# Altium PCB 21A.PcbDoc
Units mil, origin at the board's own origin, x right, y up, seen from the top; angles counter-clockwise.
Board outline 6000 x 4000 mil, 2 copper layers (Top Layer, Bottom Layer); 43 components, 21 nets, 118 pads, 2 vias.
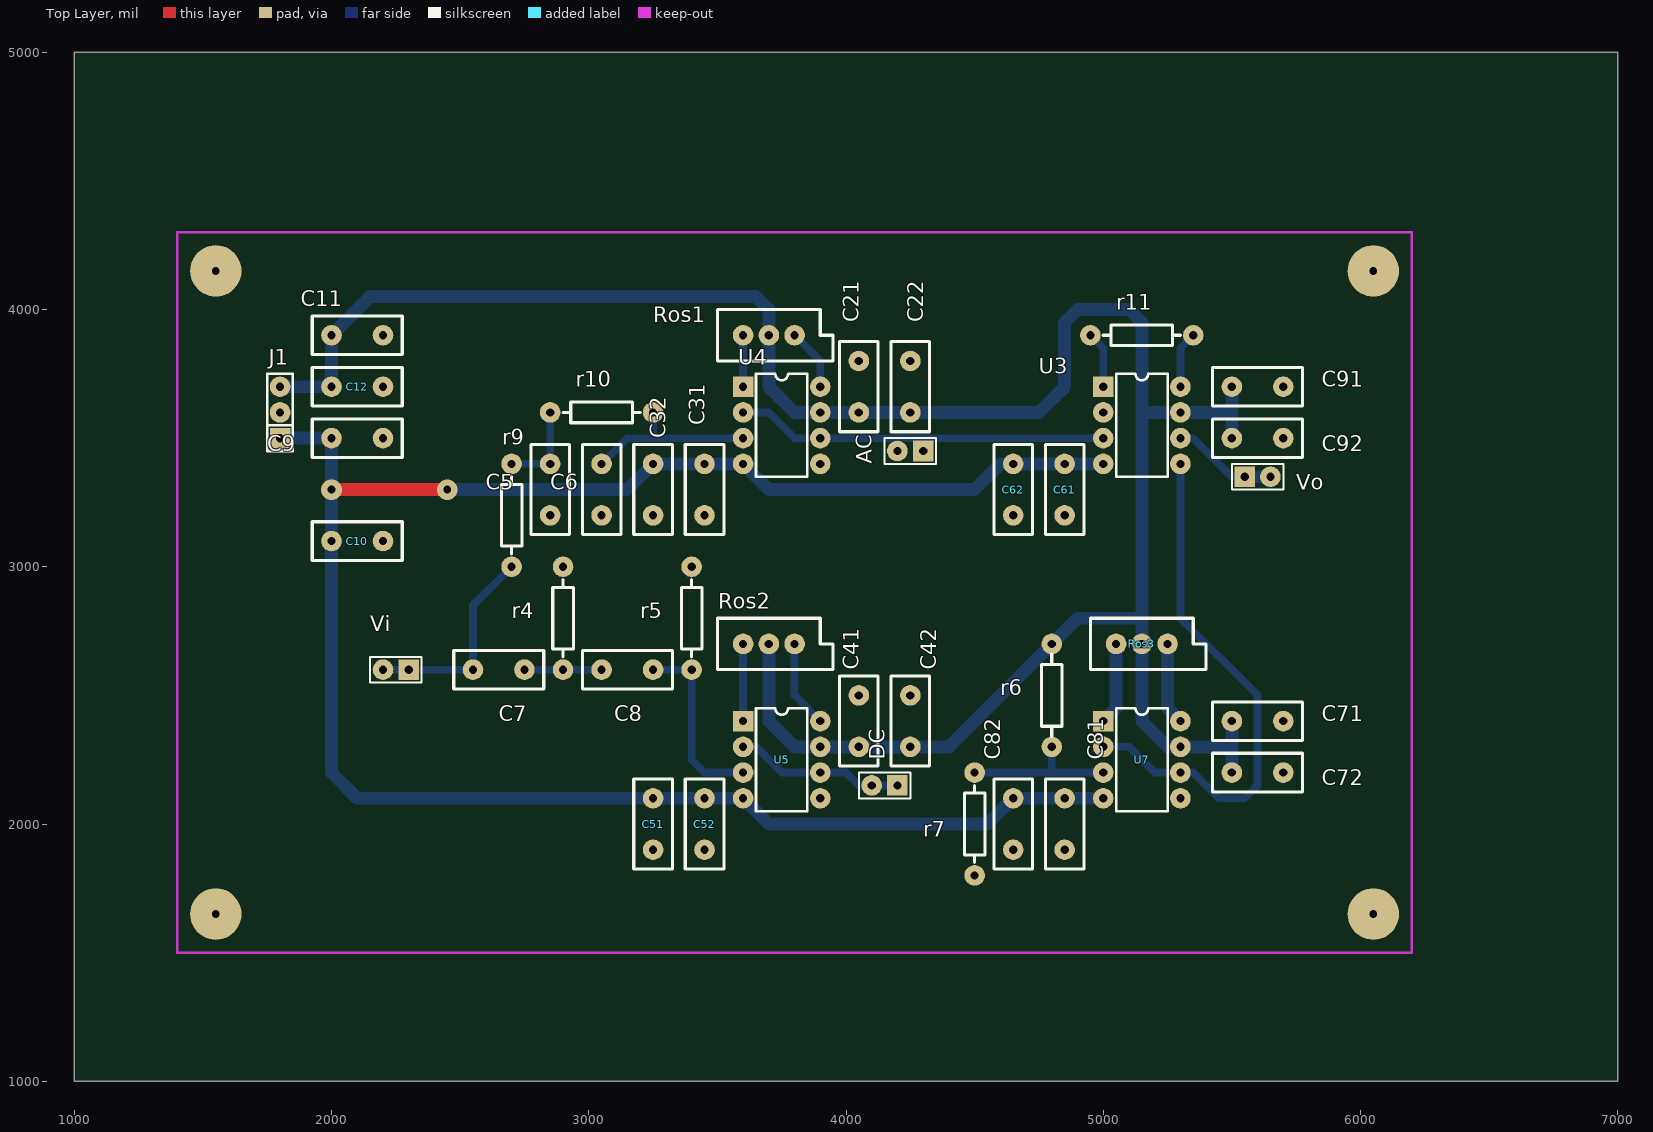
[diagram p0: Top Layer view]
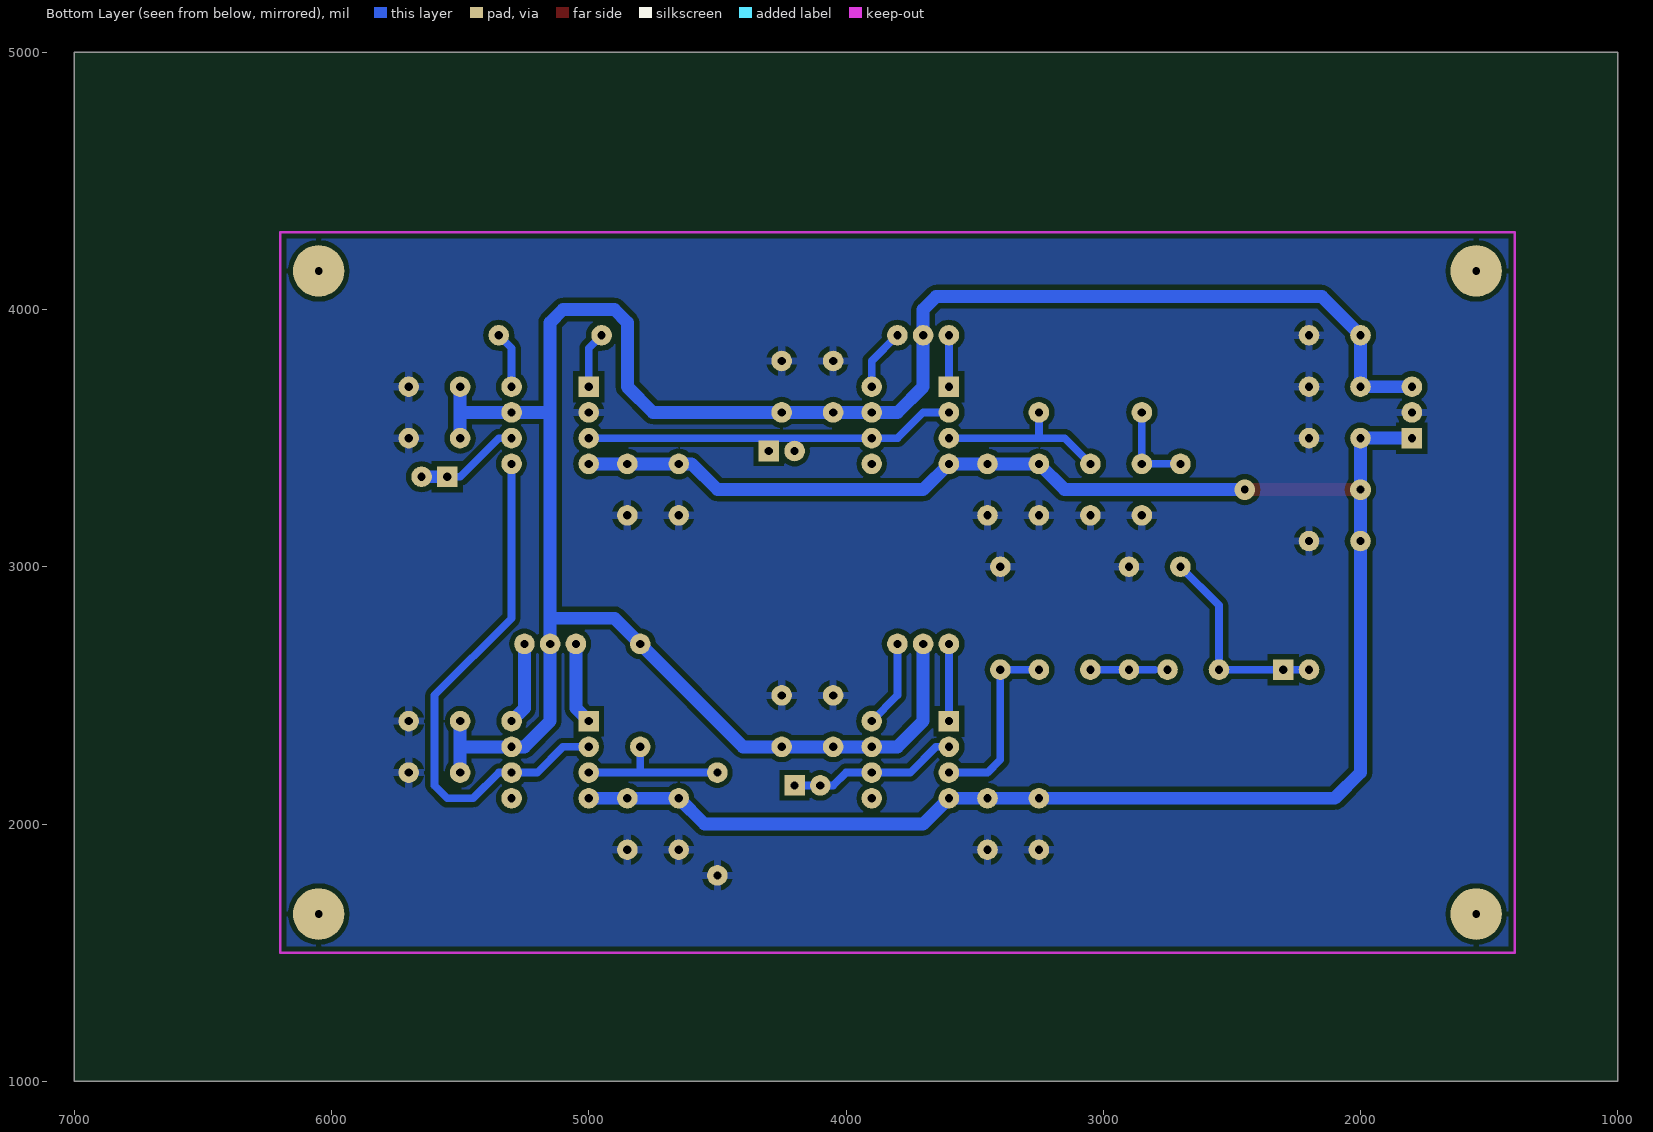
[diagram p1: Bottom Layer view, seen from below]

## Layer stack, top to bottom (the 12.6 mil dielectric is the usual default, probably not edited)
Top Layer: signal copper 1.4
Dielectric: dielectric 12.6, FR-4, Dk 4.8
Bottom Layer: signal copper 1.4

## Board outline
1000,1000 7000,1000 7000,5000 1000,5000

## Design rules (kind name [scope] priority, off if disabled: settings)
Clearance [All] p1: gap=20
PolygonConnect Viagndconnect [(InNet('GND') AND InPadClass('All Pads'))] p1: connectstyle=Relief reliefconductorwidth=30 reliefentries=4 polygonreliefangle="90 Angle"
PolygonConnect [All] p2: connectstyle=Relief reliefconductorwidth=30 reliefentries=4 polygonreliefangle="90 Angle"
RoutingVias [All] p1: holewidth=28 width=50 viastyle="Through Hole" minholewidth=28 minwidth=50 maxholewidth=28 maxwidth=50
SilkscreenOverComponentPads [IsPad] p1: minsilkscreentomaskgap=10
SolderMaskExpansion [All] p1: expansion=4
TestPointUsage [All] p1: valid=0 allowmultiple=FALSE
Testpoint [All] p1: side=3 testpointundercomponent=TRUE minsize=40 maxsize=100 preferedsize=60 minholesize=0 maxholesize=40 preferedholesize=32 testpointgrid=1 style=297 order=0123456789
Width [All] p1: maxlimit=100 minlimit=30 preferedwidth=30
23 further rules are at their usual default settings.

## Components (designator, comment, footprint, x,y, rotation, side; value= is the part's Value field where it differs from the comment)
AC "Header 2" HDR1X2 4300,3450 r180 top
C5 "Cap2" RAD0.2 2850,3400 r270 top
C6 "Cap2" RAD0.2 3050,3400 r270 top
C7 "Cap2" RAD0.2 2750,2600 r180 top
C8 "Cap2" RAD0.2 3250,2600 r180 top
C9 "Cap2" RAD0.2 2000,3500 r0 top
C10 "Cap2" RAD0.2 2000,3100 r0 top
C11 "Cap2" RAD0.2 2000,3900 r0 top
C12 "Cap2" RAD0.2 2000,3700 r0 top
C21 "Cap2" RAD0.2 4050,3600 r90 top
C22 "Cap2" RAD0.2 4250,3600 r90 top
C31 "Cap2" RAD0.2 3450,3400 r270 top
C32 "Cap2" RAD0.2 3250,3400 r270 top
C41 "Cap2" RAD0.2 4050,2500 r270 top
C42 "Cap2" RAD0.2 4250,2500 r270 top
C51 "Cap2" RAD0.2 3250,2100 r270 top
C52 "Cap2" RAD0.2 3450,2100 r270 top
C61 "Cap2" RAD0.2 4850,3400 r270 top
C62 "Cap2" RAD0.2 4650,3400 r270 top
C71 "Cap2" RAD0.2 5500,2400 r0 top
C72 "Cap2" RAD0.2 5500,2200 r0 top
C81 "Cap2" RAD0.2 4850,2100 r270 top
C82 "Cap2" RAD0.2 4650,2100 r270 top
C91 "Cap2" RAD0.2 5500,3700 r0 top
C92 "Cap2" RAD0.2 5500,3500 r0 top
DC "Header 2" HDR1X2 4200,2150 r180 top
J1 "power" SIP3 1800,3500 r90 top
r4 "Res1" AXIAL0.4 2900,2600 r90 top
r5 "Res1" AXIAL0.4 3400,2600 r90 top
r6 "Res1" AXIAL-0.4 4800,2300 r90 top
r7 "Res1" AXIAL0.4 4500,1800 r90 top
r9 "Res1" AXIAL0.4 2700,3000 r90 top
r10 "Res1" AXIAL0.4 2850,3600 r0 top
r11 "Res1" AXIAL0.4 5350,3900 r180 top
Ros1 "POT1" VR5 3600,3900 r0 top
Ros2 "POT2" VR5 3600,2700 r0 top
Ros3 "POT1" VR5 5050,2700 r0 top
U3 "AD620ANZ" DIP8 5000,3700 r0 top
U4 "opa2727" DIP8 3600,3700 r0 top
U5 "opa2727" DIP8 3600,2400 r0 top
U7 "opa2727" DIP8 5000,2400 r0 top
Vi "Header 2" HDR1X2 2300,2600 r180 top
Vo "Header 2" HDR1X2 5550,3350 r0 top

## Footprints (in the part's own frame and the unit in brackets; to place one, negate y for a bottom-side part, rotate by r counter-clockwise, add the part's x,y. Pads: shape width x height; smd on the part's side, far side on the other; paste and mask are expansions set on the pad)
AXIAL0.4 [mil]
  round 80 hole 32: 1(0,0) 2(400,0)
  silkscreen extent 50,-40 350,40
AXIAL-0.4 [mil]
  round 80 hole 32: 1(0,0) 2(400,0)
  silkscreen extent 40,-40 360,40
DIP8 [mil]
  rect 80x80 hole 32: 1(0,0)
  round 80 hole 32: 2(0,-100) 3(0,-200) 4(0,-300) 5(300,-300) 6(300,-200) 7(300,-100) 8(300,0)
  silkscreen extent 50,-350 250,50
HDR1X2 [mil] "Connector; Header; 2 Position"
  rect 80x80 hole 32: 1(0,0)
  round 80 hole 32: 2(100,0)
  silkscreen extent -50,-50 150,50
RAD0.2 [mil]
  round 80 hole 32: 1(0,0) 2(200,0)
  silkscreen extent -75,-75 275,75
SIP3 [mil]
  rect 80x80 hole 32: 1(0,0)
  round 80 hole 32: 2(100,0) 3(200,0)
  silkscreen extent -50,-50 250,50
VR5 [mil]
  round 80 hole 32: 1(0,0) 2(200,0) 3(100,0)
  silkscreen extent -100,-100 350,100

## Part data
AC DC Vi Vo: "Header, 2-Pin"
C5 C6 C7 C8 C9 C10 C11 C12 C21 C22 C31 C32 C41 C42 C51 C52 C61 C62 C71 C72 C81 C82 C91 C92: "Capacitor"
J1: library part "HEADER 3"
r4 r5 r6 r7 r9 r10 r11: "Resistor"
Ros1 Ros3: "Potentiometer"
Ros2: library part POT1, "Potentiometer"
U4 U5 U7: library part AD620ANZ

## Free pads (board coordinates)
  round 200 hole 30: 0(1550,4150) 1(1550,1650) 2(6050,1650) 3(6050,4150)

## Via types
v1: diameter 80, hole 30, Top Layer to Bottom Layer, 2 vias

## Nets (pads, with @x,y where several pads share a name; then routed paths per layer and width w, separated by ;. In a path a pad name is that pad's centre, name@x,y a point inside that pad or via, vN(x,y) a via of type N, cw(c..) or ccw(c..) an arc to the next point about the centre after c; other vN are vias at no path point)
+5: C11.1 C12.1 C21.1 C22.1 C41.2 C42.2 C71.1 C72.1 C91.1 C92.1 J1.3 r6.2 Ros1.3 Ros2.3 Ros3.3 U3.7 U4.7 U5.7 U7.7 | length 8997.1
  Bottom Layer w50: J1.3 C12.1 C11.1 2150,4050 3650,4050 3700,4000 Ros1.3 3700,3700 3800,3600 U4.7 C21.1 C22.1 4750,3600 4850,3700 4850,3950 4900,4000 5100,4000 5150,3950 5150,3600 ; Ros2.3 3700,2400 3800,2300 U5.7 C41.2 C42.2 4400,2300 r6.2 4900,2800 5150,2800 ; C72.1 5500,2300 ; C71.1 5500,2300 ; C92.1 5500,3600 ; C91.1 5500,3600 ; 5150,2800 Ros3.3 5150,2400 5250,2300 U7.7 5500,2300 ; 5150,2800 5150,3600 ; 5150,3600 U3.7 5500,3600
-5: C9.1 C10.1 C31.1 C32.1 C51.1 C52.1 C61.1 C62.1 C81.1 C82.1 J1.1 U3.4 U4.4 U5.4 U7.4 | length 7748.5
  Top Layer w50: v1(2000,3300) v1(2450,3300)
  Bottom Layer w50: J1.1 C9.1 v1(2000,3300) C10.1 2000,2200 2100,2100 C51.1 C52.1 U5.4 3700,2000 4550,2000 C82.1 C81.1 U7.4 ; v1(2450,3300) 3150,3300 C32.1 C31.1 U4.4 3700,3300 4500,3300 4600,3400 C62.1 C61.1 U3.4
GND: C5.2 C6.2 C9.2 C10.2 C11.2 C12.2 C21.2 C22.2 C31.2 C32.2 C41.1 C42.1 C51.2 C52.2 C61.2 C62.2 C71.2 C72.2 C81.2 C82.2 C91.2 C92.2 J1.2 r4.2 r5.2 r7.1 U3.2
NetAC_1: AC.1 AC.2 U3.3 U4.2 U4.6 | length 1441.4
  Bottom Layer w30: U4.2 3700,3600 3800,3500 U4.6 U3.3
NetC5_1: C5.1 r9.2 r10.1 | length 350
  Bottom Layer w30: r9.2 C5.1 r10.1
NetC6_1: C6.1 r10.2 U4.3 | length 691.4
  Bottom Layer w30: C6.1 3150,3500 3250,3500 ; r10.2 3250,3500 ; U4.3 3250,3500
NetC7_1: C7.1 C8.2 r4.1 | length 250
  Bottom Layer w30: 2800,2600 r4.1 C8.2
NetC7_2: C7.2 r9.1 Vi.1 Vi.2 | length 812.1
  Bottom Layer w30: Vi.2 Vi.1 C7.2 2550,2850 r9.1
NetC8_1: C8.1 r5.1 U5.3 | length 720.7
  Bottom Layer w30: C8.1 r5.1 3400,2250 3450,2200 U5.3
NetDC_1: DC.1 DC.2 U5.2 U5.6 | length 662.1
  Bottom Layer w30: U5.2 3650,2300 3750,2200 U5.6 4000,2200 4050,2150 DC.2 DC.1
Netr6_1: r6.1 r7.2 U7.3 | length 600
  Bottom Layer w30: r7.2 4800,2200 ; r6.1 4800,2200 ; U7.3 4800,2200
Netr11_1: r11.1 U3.8 | length 220.7
  Bottom Layer w30: U3.8 5300,3850 r11.1
Netr11_2: r11.2 U3.1 | length 220.7
  Bottom Layer w30: r11.2 5000,3850 U3.1
NetRos1_1: Ros1.1 U4.1 | length 200
  Bottom Layer w30: U4.1 Ros1.1
NetRos1_2: Ros1.2 U4.8 | length 241.4
  Bottom Layer w30: Ros1.2 3900,3800 U4.8
NetRos2_1: Ros2.1 U5.1 | length 300
  Bottom Layer w30: U5.1 Ros2.1
NetRos2_2: Ros2.2 U5.8 | length 341.4
  Bottom Layer w30: Ros2.2 3800,2500 U5.8
NetRos3_1: Ros3.1 U7.1 | length 320.7
  Bottom Layer w50: U7.1 5050,2450 Ros3.1
NetRos3_2: Ros3.2 U7.8 | length 320.7
  Bottom Layer w50: Ros3.2 5250,2450 U7.8
NetU3_6: U3.6 Vo.1 Vo.2 | length 412.1
  Bottom Layer w30: U3.6 5350,3500 5500,3350 Vo.1
  Bottom Layer w50: Vo.1 Vo.2
VREF: U3.5 U7.2 U7.6 | length 2077.8
  Bottom Layer w30: U7.2 5100,2300 5200,2200 U7.6 5350,2200 5450,2100 5550,2100 5600,2150 5600,2500 5300,2800 U3.5
pads on no net: U4.5 U5.5 U7.5

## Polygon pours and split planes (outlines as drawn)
GND on Bottom Layer "Bottom Layer-No Net" (solid, pour order 1000): 1400,4300 6200,4300 6200,1500 1400,1500

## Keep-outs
Keep-Out Layer:
  lines w10: 1400,1500 1400,4300 1600,4300 6200,4300 6200,1500 1600,1500 1400,1500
